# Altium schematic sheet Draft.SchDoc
size A4
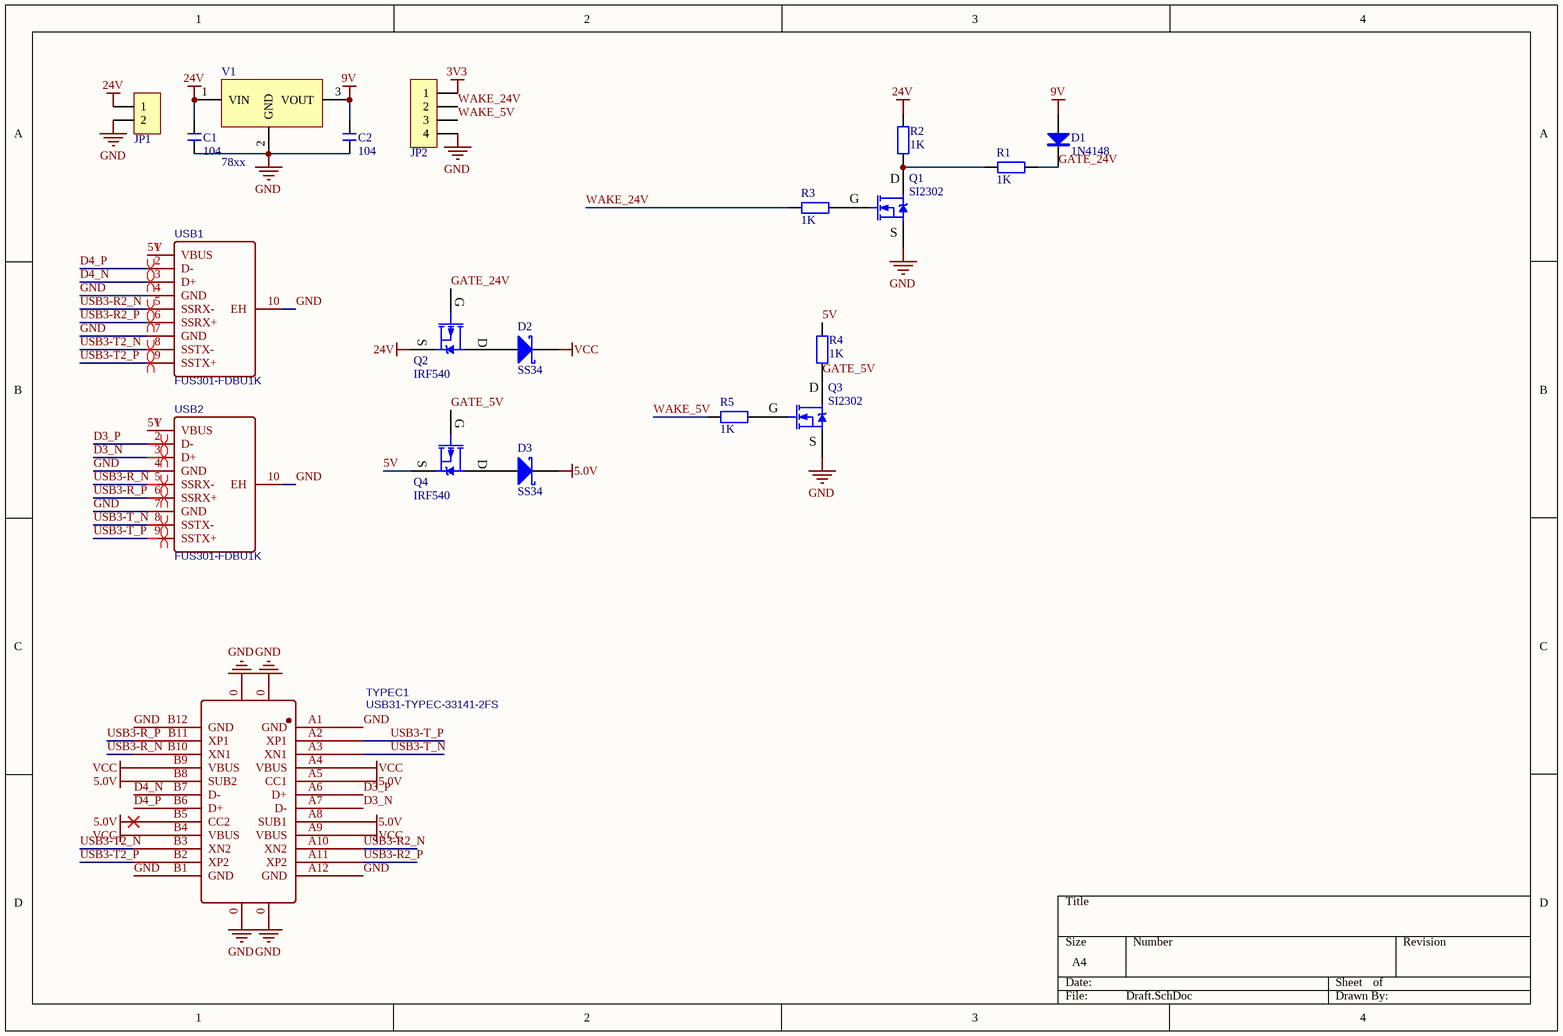
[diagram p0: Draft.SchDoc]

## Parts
C1  104  [C 1206_L]
C2  104  [C 1206_L]
D1  1N4148  [MINI_MELF (LL34)]
D2  SS34  [SMC]
D3  SS34  [SMC]
JP1  HDR-1X2  [XT30]  (value not drawn)
JP2  HDR-1X4  [XH2.54-LI-4P]  (value not drawn)
Q1  SI2302  [SOT23-3N]
Q2  IRF540  [TO252]
Q3  SI2302  [SOT23-3N]
Q4  IRF540  [TO252]
R1  1K  [R 0603_L]
R2  1K  [R 0603_L]
R3  1K  [R 0603_L]
R4  1K  [R 0603_L]
R5  1K  [R 0603_L]
TYPEC1  USB31-TYPEC-33141-2FS  [TypeC-Chaban24P]
USB1  FUS301-FDBU1K  [USB3.0-A-TH_FUS301-FDBU1K]
USB2  FUS301-FDBU1K  [USB3.0-A-TH_FUS301-FDBU1K]
V1  78xx  [TO252]

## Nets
3V3: JP2.1
5.0V: D3.2(K) TYPEC1.A5(CC1) TYPEC1.A8(SUB1) TYPEC1.B5(CC2) TYPEC1.B8(SUB2)
9V: C2.2 D1.1(A) V1.3(VOUT)
24V: C1.2 JP1.1 Q2.3(S) R2.2 V1.1(VIN)
GND: C1.1 C2.1 JP1.2 JP2.4 Q1.2(S) Q3.2(S) TYPEC1.0 TYPEC1.A1(GND) TYPEC1.A12(GND) TYPEC1.B1(GND) TYPEC1.B12(GND) USB1.4(GND) USB1.7(GND) USB1.10(EH) USB2.4(GND) USB2.7(GND) USB2.10(EH) V1.2(GND)
VCC: D2.2(K) TYPEC1.A4(VBUS) TYPEC1.A9(VBUS) TYPEC1.B4(VBUS) TYPEC1.B9(VBUS)
5V: Q4.3(S) R4.2 USB1.1(VBUS) USB2.1(VBUS)
D3_N: TYPEC1.A7(D-) USB2.3(D+)
D3_P: TYPEC1.A6(D+) USB2.2(D-)
D4_N: TYPEC1.B7(D-) USB1.3(D+)
D4_P: TYPEC1.B6(D+) USB1.2(D-)
GATE_5V: Q3.3(D) Q4.1(G) R4.1
GATE_24V: D1.2(K) Q2.1(G) R1.1
USB3-R2_N: TYPEC1.A10(XN2) USB1.5(SSRX-)
USB3-R2_P: TYPEC1.A11(XP2) USB1.6(SSRX+)
USB3-R_N: TYPEC1.B10(XN1) USB2.5(SSRX-)
USB3-R_P: TYPEC1.B11(XP1) USB2.6(SSRX+)
USB3-T2_N: TYPEC1.B3(XN2) USB1.8(SSTX-)
USB3-T2_P: TYPEC1.B2(XP2) USB1.9(SSTX+)
USB3-T_N: TYPEC1.A3(XN1) USB2.8(SSTX-)
USB3-T_P: TYPEC1.A2(XP1) USB2.9(SSTX+)
WAKE_5V: JP2.3 R5.1
WAKE_24V: JP2.2 R3.1
NetD2_1: D2.1(A) Q2.2(D)
NetD3_1: D3.1(A) Q4.2(D)
NetQ1_1: Q1.1(G) R3.2
NetQ1_3: Q1.3(D) R1.2 R2.1
NetQ3_1: Q3.1(G) R5.2

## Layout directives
differential pair: D3_N, D3_P, D4_N, D4_P, USB3-R2_N, USB3-R2_P, USB3-R_N, USB3-R_P, USB3-T2_N, USB3-T2_P, USB3-T_N, USB3-T_P

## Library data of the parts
C1 C2 = C: 贴片电容; BOM名称: 无极性贴片电容; 淘宝ID: 封装库来自淘宝 ID：黄晶宝石
D1 = 1N4148: 开关二极管; BOM名称: 高速开关二极管; 淘宝ID: 封装库来自淘宝 ID：黄晶宝石
D2 D3 = SS34: 肖特基二极管; 属性: 40V/3A
JP1 = Header 2: 2P接插件; 版权归属: 封装库来自淘宝 ID：黄晶宝石
JP2 = Header 4: 4P接插件; 版权归属: 封装库来自淘宝 ID：黄晶宝石
Q1 Q3 = SI2302: N沟道场效应管
Q2 Q4 = IRF540: P沟场效应管
R1-R5 = R: 贴片电阻; 版权归属: 来自淘宝 ID：黄晶宝石
TYPEC1 = USB31-TYPEC-33141-2FS: BOM_Manufacturer: XKB Enterprise; Contributor: LCSC
USB1 USB2 = FUS301-FDBU1K: BOM_Manufacturer: TXGA; Contributor: LCSC
V1 = 78xx: 线性稳压芯片; 淘宝ID: 封装库来自淘宝 ID：黄晶宝石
